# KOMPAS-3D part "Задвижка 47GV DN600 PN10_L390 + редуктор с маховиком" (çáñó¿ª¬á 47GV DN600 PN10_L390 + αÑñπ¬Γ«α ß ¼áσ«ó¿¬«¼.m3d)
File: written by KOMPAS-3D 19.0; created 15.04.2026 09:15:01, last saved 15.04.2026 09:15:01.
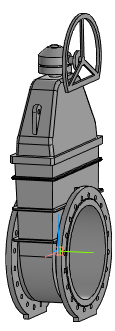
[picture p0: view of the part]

Document properties: Автор: Энергия; Полное имя файла: ..\..\Задвижка 47GV DN600 PN10_L390 + редуктор с маховиком.a3d

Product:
- Part/product: Задвижка 47GV DN600 PN10_L390 + редуктор с маховиком
    Масса: 1548.29

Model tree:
1. Операция без истории:1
